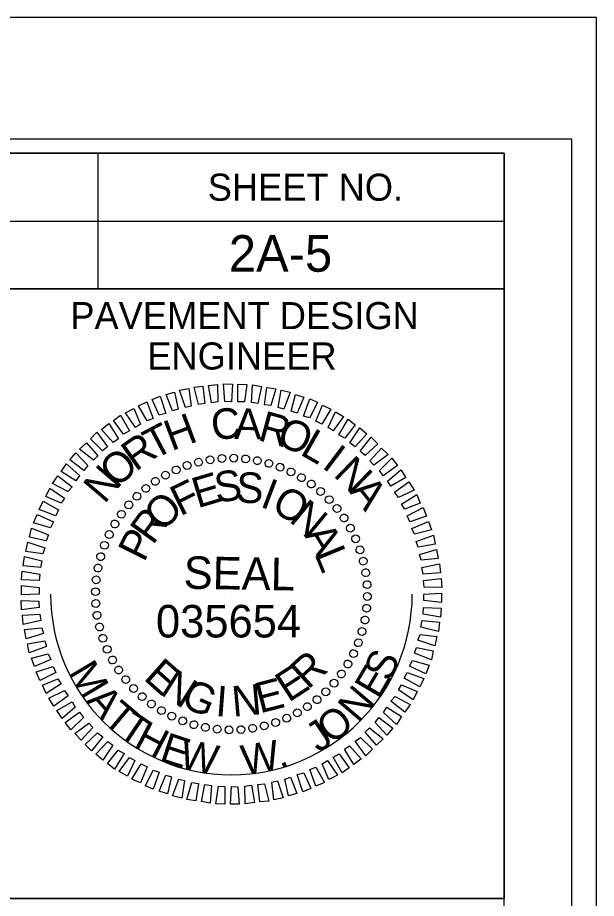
# Model space of a CAD drawing. Extents: x 957297 to 961629, y 830661 to 840840.
# Drawn here: x 960288 to 960394.8, y 835525.5 to 835688 of the extents above; entities that cross this region are included whole.
import ezdxf

# ---------------------------------------------------------------- set-up
doc = ezdxf.new("R2010")
doc.units = 0
for name, color, linetype in [('Scratch_Level_0', 7, 'Continuous'), ('Sheet Data Field CELL', 7, 'Continuous'), ('Sheet Plot Border Inside CELL', 7, 'Continuous'), ('Sheet Plot Border Outside CELL', 7, 'Continuous'), ('Sheet Professional Seal CELL', 7, 'Continuous'), ('Sheet Profile Grid Minor CELL', 7, 'Continuous'), ('Sheet Sticker Exception Certification CELL', 7, 'Continuous'), ('Sheet Typical CELL', 7, 'Continuous')]:
    doc.layers.add(name, color=color, linetype=linetype)

msp = doc.modelspace()

# ---------------------------------------------------------------- linework, layer by layer
at = {"layer": 'Scratch_Level_0'}
msp.add_arc((960327.47, 835581.64), 33.36, 180, 360, dxfattribs=at)
at = {"layer": 'Sheet Plot Border Inside CELL'}
msp.add_lwpolyline([(960390.3, 835665.58), (958723.8, 835665.58), (958723.8, 834610.48), (960390.3, 834610.48)], close=True, dxfattribs=at)
at = {"layer": 'Sheet Plot Border Outside CELL'}
msp.add_lwpolyline([(960394.8, 835688.03), (958710.8, 835688.03), (958710.8, 834588.03), (960394.8, 834588.03)], close=True, dxfattribs=at)
at = {"layer": 'Sheet Professional Seal CELL'}
for p, q in [((960321.37, 835605.99), (960321.37, 835605.99)), ((960323.57, 835606.39), (960323.57, 835606.39)), ((960325.72, 835606.69), (960325.72, 835606.69)), ((960327.92, 835606.74), (960327.92, 835606.74)), ((960330.12, 835606.59), (960330.12, 835606.59)), ((960332.27, 835606.24), (960332.27, 835606.24)), ((960334.37, 835605.79), (960334.37, 835605.79)), ((960317.27, 835604.59), (960317.27, 835604.59)), ((960319.27, 835605.39), (960319.27, 835605.39)), ((960336.47, 835605.09), (960336.47, 835605.09)), ((960338.47, 835604.19), (960338.47, 835604.19)), ((960315.32, 835603.59), (960315.32, 835603.59)), ((960340.42, 835603.19), (960340.42, 835603.19)), ((960311.67, 835601.19), (960311.67, 835601.19)), ((960313.42, 835602.44), (960313.42, 835602.44)), ((960342.22, 835601.94), (960342.22, 835601.94)), ((960310.02, 835599.69), (960310.02, 835599.69)), ((960343.97, 835600.59), (960343.97, 835600.59)), ((960308.52, 835598.14), (960308.52, 835598.14)), ((960345.52, 835599.09), (960345.52, 835599.09)), ((960307.17, 835596.39), (960307.17, 835596.39)), ((960347.02, 835597.44), (960347.02, 835597.44)), ((960305.92, 835594.59), (960305.92, 835594.59)), ((960348.27, 835595.69), (960348.27, 835595.69)), ((960349.42, 835593.79), (960349.42, 835593.79)), ((960304.92, 835592.64), (960304.92, 835592.64)), ((960350.42, 835591.84), (960350.42, 835591.84)), ((960304.02, 835590.64), (960304.02, 835590.64)), ((960351.22, 835589.84), (960351.22, 835589.84)), ((960303.32, 835588.54), (960303.32, 835588.54)), ((960302.87, 835586.44), (960302.87, 835586.44)), ((960351.82, 835587.74), (960351.82, 835587.74)), ((960352.22, 835585.54), (960352.22, 835585.54)), ((960302.52, 835584.29), (960302.52, 835584.29)), ((960352.52, 835583.39), (960352.52, 835583.39)), ((960302.37, 835582.09), (960302.37, 835582.09)), ((960327.47, 835581.64), (960327.47, 835581.64)), ((960302.42, 835579.89), (960302.42, 835579.89)), ((960352.57, 835581.19), (960352.57, 835581.19)), ((960352.42, 835578.99), (960352.42, 835578.99)), ((960302.72, 835577.74), (960302.72, 835577.74)), ((960352.07, 835576.84), (960352.07, 835576.84)), ((960303.12, 835575.54), (960303.12, 835575.54)), ((960303.72, 835573.44), (960303.72, 835573.44)), ((960351.62, 835574.74), (960351.62, 835574.74)), ((960350.92, 835572.64), (960350.92, 835572.64)), ((960304.52, 835571.44), (960304.52, 835571.44)), ((960350.02, 835570.64), (960350.02, 835570.64)), ((960305.52, 835569.49), (960305.52, 835569.49)), ((960349.02, 835568.69), (960349.02, 835568.69)), ((960306.67, 835567.59), (960306.67, 835567.59)), ((960347.77, 835566.89), (960347.77, 835566.89)), ((960307.92, 835565.84), (960307.92, 835565.84)), ((960346.42, 835565.14), (960346.42, 835565.14)), ((960309.42, 835564.19), (960309.42, 835564.19)), ((960344.92, 835563.59), (960344.92, 835563.59)), ((960310.97, 835562.69), (960310.97, 835562.69)), ((960343.27, 835562.09), (960343.27, 835562.09)), ((960312.72, 835561.34), (960312.72, 835561.34)), ((960341.52, 835560.84), (960341.52, 835560.84)), ((960314.52, 835560.09), (960314.52, 835560.09)), ((960316.47, 835559.09), (960316.47, 835559.09)), ((960337.67, 835558.69), (960337.67, 835558.69)), ((960339.62, 835559.69), (960339.62, 835559.69)), ((960318.47, 835558.19), (960318.47, 835558.19)), ((960320.57, 835557.49), (960320.57, 835557.49)), ((960322.67, 835557.04), (960322.67, 835557.04)), ((960333.57, 835557.29), (960333.57, 835557.29)), ((960335.67, 835557.89), (960335.67, 835557.89)), ((960324.82, 835556.69), (960324.82, 835556.69)), ((960327.02, 835556.54), (960327.02, 835556.54)), ((960329.22, 835556.59), (960329.22, 835556.59)), ((960331.37, 835556.89), (960331.37, 835556.89))]:
    msp.add_line(p, q, dxfattribs=at)
for points in [[(960326.27, 835617.19), (960326.02, 835620.44), (960327.67, 835620.39), (960327.47, 835617.14)], [(960316.57, 835615.44), (960315.42, 835618.44), (960316.97, 835618.89), (960317.62, 835615.79)], [(960318.97, 835616.09), (960317.92, 835619.24), (960319.62, 835619.59), (960320.02, 835616.34)], [(960321.37, 835616.64), (960320.57, 835619.84), (960322.22, 835619.99), (960322.57, 835616.79)], [(960323.77, 835616.94), (960323.22, 835620.14), (960324.92, 835620.34), (960324.97, 835617.09)], [(960328.67, 835617.14), (960328.67, 835620.39), (960330.32, 835620.34), (960329.87, 835617.09)], [(960331.17, 835616.99), (960331.37, 835620.24), (960333.02, 835619.94), (960332.37, 835616.79)], [(960333.57, 835616.59), (960334.02, 835619.79), (960335.67, 835619.54), (960334.77, 835616.44)], [(960336.12, 835616.04), (960336.62, 835619.29), (960338.32, 835618.89), (960337.17, 835615.79)], [(960314.12, 835614.64), (960312.82, 835617.54), (960314.32, 835618.14), (960315.37, 835614.94)], [(960338.52, 835615.39), (960339.27, 835618.49), (960340.82, 835617.99), (960339.57, 835615.04)], [(960340.77, 835614.49), (960341.92, 835617.64), (960343.32, 835617.04), (960341.92, 835614.14)], [(960309.77, 835612.39), (960307.92, 835615.09), (960309.47, 835615.89), (960310.72, 835612.99)], [(960311.92, 835613.59), (960310.32, 835616.39), (960311.87, 835617.09), (960313.02, 835614.04)], [(960343.02, 835613.54), (960344.27, 835616.49), (960345.82, 835615.79), (960344.12, 835612.99)], [(960307.57, 835611.14), (960305.72, 835613.69), (960307.02, 835614.64), (960308.67, 835611.74)], [(960345.32, 835612.39), (960346.67, 835615.24), (960348.17, 835614.39), (960346.27, 835611.79)], [(960347.27, 835611.04), (960349.02, 835613.94), (960350.32, 835612.89), (960348.37, 835610.44)], [(960305.67, 835609.64), (960303.52, 835612.04), (960304.87, 835613.09), (960306.62, 835610.29)], [(960349.32, 835609.54), (960351.17, 835612.29), (960352.47, 835611.19), (960350.27, 835608.84)], [(960303.67, 835608.09), (960301.47, 835610.29), (960302.67, 835611.49), (960304.62, 835608.79)], [(960302.02, 835606.34), (960299.47, 835608.39), (960300.72, 835609.54), (960302.82, 835607.14)], [(960351.22, 835607.99), (960353.27, 835610.59), (960354.47, 835609.39), (960352.17, 835607.24)], [(960300.27, 835604.44), (960297.67, 835606.39), (960298.77, 835607.69), (960300.97, 835605.34)], [(960353.02, 835606.24), (960355.17, 835608.59), (960356.37, 835607.39), (960353.77, 835605.44)], [(960354.77, 835604.44), (960357.07, 835606.69), (960358.12, 835605.34), (960355.47, 835603.44)], [(960298.77, 835602.54), (960296.07, 835604.24), (960297.02, 835605.69), (960299.42, 835603.49)], [(960356.27, 835602.49), (960358.72, 835604.59), (960359.67, 835603.14), (960356.87, 835601.54)], [(960297.27, 835600.54), (960294.47, 835602.04), (960295.47, 835603.44), (960298.07, 835601.44)], [(960296.07, 835598.39), (960293.22, 835599.64), (960293.97, 835601.19), (960296.67, 835599.34)], [(960357.57, 835600.44), (960360.22, 835602.34), (960361.17, 835600.84), (960358.27, 835599.44)], [(960358.87, 835598.24), (960361.67, 835599.99), (960362.32, 835598.44), (960359.47, 835597.29)], [(960295.07, 835596.09), (960291.97, 835597.24), (960292.72, 835598.79), (960295.57, 835597.19)], [(960294.07, 835593.89), (960290.97, 835594.79), (960291.62, 835596.34), (960294.62, 835594.94)], [(960359.87, 835596.09), (960362.82, 835597.59), (960363.47, 835595.99), (960360.37, 835594.99)], [(960360.77, 835593.74), (960363.82, 835595.04), (960364.37, 835593.49), (960361.27, 835592.69)], [(960293.32, 835591.49), (960290.22, 835592.14), (960290.57, 835593.79), (960293.72, 835592.54)], [(960292.67, 835589.09), (960289.57, 835589.49), (960289.92, 835591.19), (960293.07, 835590.14)], [(960361.57, 835591.34), (960364.77, 835592.49), (960365.07, 835590.84), (960361.92, 835590.29)], [(960362.17, 835588.94), (960365.32, 835589.89), (960365.62, 835588.19), (960362.47, 835587.89)], [(960292.27, 835586.54), (960289.07, 835586.84), (960289.27, 835588.54), (960292.52, 835587.74)], [(960362.62, 835586.54), (960365.87, 835587.24), (960366.02, 835585.54), (960362.82, 835585.34)], [(960292.02, 835584.14), (960288.77, 835584.24), (960288.87, 835585.89), (960292.12, 835585.34)], [(960291.97, 835581.64), (960288.72, 835581.49), (960288.72, 835583.19), (960291.97, 835582.84)], [(960362.92, 835584.14), (960366.17, 835584.54), (960366.27, 835582.84), (960363.02, 835582.94)], [(960362.97, 835581.64), (960366.22, 835581.79), (960366.22, 835580.09), (960362.97, 835580.44)], [(960292.02, 835579.14), (960288.77, 835578.74), (960288.67, 835580.44), (960291.92, 835580.34)], [(960362.92, 835579.14), (960366.17, 835579.04), (960366.07, 835577.39), (960362.82, 835577.94)], [(960292.32, 835576.74), (960289.07, 835576.04), (960288.92, 835577.74), (960292.12, 835577.94)], [(960362.67, 835576.74), (960365.87, 835576.44), (960365.67, 835574.74), (960362.42, 835575.54)], [(960292.77, 835574.34), (960289.62, 835573.39), (960289.32, 835575.09), (960292.47, 835575.39)], [(960362.27, 835574.19), (960365.37, 835573.79), (960365.02, 835572.09), (960361.87, 835573.14)], [(960293.37, 835571.94), (960290.17, 835570.79), (960289.87, 835572.44), (960293.02, 835572.99)], [(960361.62, 835571.79), (960364.72, 835571.14), (960364.37, 835569.49), (960361.22, 835570.74)], [(960294.17, 835569.54), (960291.12, 835568.24), (960290.57, 835569.79), (960293.67, 835570.59)], [(960360.87, 835569.39), (960363.97, 835568.49), (960363.32, 835566.94), (960360.32, 835568.34)], [(960295.07, 835567.19), (960292.12, 835565.69), (960291.47, 835567.29), (960294.57, 835568.29)], [(960359.87, 835567.19), (960362.97, 835566.04), (960362.22, 835564.49), (960359.37, 835566.09)], [(960296.07, 835565.04), (960293.27, 835563.29), (960292.62, 835564.84), (960295.47, 835565.99)], [(960297.37, 835562.84), (960294.72, 835560.94), (960293.77, 835562.44), (960296.67, 835563.84)], [(960358.87, 835564.89), (960361.72, 835563.64), (960360.97, 835562.09), (960358.27, 835563.94)], [(960357.67, 835562.74), (960360.47, 835561.24), (960359.47, 835559.84), (960356.87, 835561.84)], [(960298.67, 835560.79), (960296.22, 835558.69), (960295.27, 835560.14), (960298.07, 835561.74)], [(960356.17, 835560.74), (960358.87, 835559.04), (960357.92, 835557.59), (960355.52, 835559.79)], [(960300.17, 835558.84), (960297.87, 835556.59), (960296.82, 835557.94), (960299.47, 835559.84)], [(960354.67, 835558.84), (960357.27, 835556.89), (960356.17, 835555.59), (960353.97, 835557.94)], [(960301.92, 835557.04), (960299.77, 835554.69), (960298.57, 835555.89), (960301.17, 835557.84)], [(960303.72, 835555.29), (960301.67, 835552.69), (960300.47, 835553.89), (960302.77, 835556.04)], [(960352.92, 835556.94), (960355.47, 835554.89), (960354.22, 835553.74), (960352.12, 835556.14)], [(960305.62, 835553.74), (960303.77, 835550.99), (960302.47, 835552.09), (960304.67, 835554.44)], [(960351.27, 835555.19), (960353.47, 835552.99), (960352.27, 835551.79), (960350.32, 835554.49)], [(960307.67, 835552.24), (960305.92, 835549.34), (960304.62, 835550.39), (960306.57, 835552.84)], [(960347.37, 835552.14), (960349.22, 835549.59), (960347.92, 835548.64), (960346.27, 835551.54)], [(960349.27, 835553.64), (960351.42, 835551.24), (960350.07, 835550.19), (960348.32, 835552.99)], [(960309.62, 835550.89), (960308.27, 835548.04), (960306.77, 835548.89), (960308.67, 835551.49)], [(960345.17, 835550.89), (960347.02, 835548.19), (960345.47, 835547.39), (960344.22, 835550.29)], [(960311.92, 835549.74), (960310.67, 835546.79), (960309.12, 835547.49), (960310.82, 835550.29)], [(960314.17, 835548.79), (960313.02, 835545.64), (960311.62, 835546.24), (960313.02, 835549.14)], [(960343.02, 835549.69), (960344.62, 835546.89), (960343.07, 835546.19), (960341.92, 835549.24)], [(960316.42, 835547.89), (960315.67, 835544.79), (960314.12, 835545.29), (960315.37, 835548.24)], [(960318.82, 835547.24), (960318.32, 835543.99), (960316.62, 835544.39), (960317.77, 835547.49)], [(960338.37, 835547.84), (960339.52, 835544.84), (960337.97, 835544.39), (960337.32, 835547.49)], [(960340.82, 835548.64), (960342.12, 835545.74), (960340.62, 835545.14), (960339.57, 835548.34)], [(960321.37, 835546.69), (960320.92, 835543.49), (960319.27, 835543.74), (960320.17, 835546.84)], [(960323.77, 835546.29), (960323.57, 835543.04), (960321.92, 835543.34), (960322.57, 835546.49)], [(960326.27, 835546.14), (960326.27, 835542.89), (960324.62, 835542.94), (960325.07, 835546.19)], [(960328.67, 835546.09), (960328.92, 835542.84), (960327.27, 835542.89), (960327.47, 835546.14)], [(960331.17, 835546.34), (960331.72, 835543.14), (960330.02, 835542.94), (960329.97, 835546.19)], [(960333.57, 835546.64), (960334.37, 835543.44), (960332.72, 835543.29), (960332.37, 835546.49)], [(960335.97, 835547.19), (960337.02, 835544.04), (960335.32, 835543.69), (960334.92, 835546.94)]]:
    msp.add_lwpolyline(points, close=True, dxfattribs=at)
for centre, major_axis in [((960325.72, 835606.66), (-0.05, 0.718)), ((960327.9, 835606.72), (0.013, 0.72)), ((960319.3, 835605.36), (-0.234, 0.681)), ((960321.4, 835605.98), (-0.174, 0.699)), ((960323.54, 835606.41), (-0.113, 0.711)), ((960330.09, 835606.58), (0.075, 0.716)), ((960332.25, 835606.26), (0.137, 0.707)), ((960334.38, 835605.75), (0.198, 0.692)), ((960336.45, 835605.06), (0.258, 0.672)), ((960315.31, 835603.58), (-0.349, 0.63)), ((960317.27, 835604.55), (-0.293, 0.658)), ((960338.46, 835604.18), (0.316, 0.647)), ((960313.44, 835602.43), (-0.403, 0.597)), ((960340.38, 835603.14), (0.371, 0.617)), ((960342.21, 835601.93), (0.423, 0.582)), ((960311.68, 835601.13), (-0.453, 0.56)), ((960343.92, 835600.57), (0.472, 0.543)), ((960310.04, 835599.68), (-0.5, 0.518)), ((960345.51, 835599.06), (0.518, 0.5)), ((960308.54, 835598.1), (-0.543, 0.472)), ((960346.96, 835597.43), (0.56, 0.453)), ((960307.18, 835596.38), (-0.582, 0.423)), ((960348.26, 835595.67), (0.597, 0.403)), ((960305.97, 835594.56), (-0.617, 0.371)), ((960349.4, 835593.8), (0.63, 0.349)), ((960304.92, 835592.64), (-0.647, 0.316)), ((960304.05, 835590.63), (-0.672, 0.258)), ((960350.38, 835591.84), (0.658, 0.293)), ((960351.18, 835589.81), (0.681, 0.234)), ((960303.36, 835588.55), (-0.692, 0.198)), ((960351.8, 835587.71), (0.699, 0.174)), ((960302.85, 835586.43), (-0.707, 0.137)), ((960352.24, 835585.57), (0.711, 0.113)), ((960302.52, 835584.26), (-0.716, 0.075)), ((960352.49, 835583.39), (0.718, 0.05)), ((960302.39, 835582.08), (-0.72, 0.013)), ((960352.54, 835581.2), (0.72, -0.013)), ((960302.45, 835579.89), (-0.718, -0.05)), ((960352.41, 835579.02), (0.716, -0.075)), ((960302.69, 835577.72), (-0.711, -0.113)), ((960352.09, 835576.86), (0.707, -0.137)), ((960303.13, 835575.57), (-0.699, -0.174)), ((960351.57, 835574.73), (0.692, -0.198)), ((960303.75, 835573.48), (-0.681, -0.234)), ((960350.88, 835572.65), (0.672, -0.258)), ((960304.55, 835571.44), (-0.658, -0.293)), ((960305.53, 835569.48), (-0.63, -0.349)), ((960350.01, 835570.65), (0.647, -0.316)), ((960306.67, 835567.62), (-0.597, -0.403)), ((960348.96, 835568.72), (0.617, -0.371)), ((960347.76, 835566.9), (0.582, -0.423)), ((960307.98, 835565.86), (-0.56, -0.453)), ((960346.39, 835565.19), (0.543, -0.472)), ((960309.43, 835564.22), (-0.518, -0.5)), ((960311.01, 835562.71), (-0.472, -0.543)), ((960344.89, 835563.6), (0.5, -0.518)), ((960312.72, 835561.35), (-0.423, -0.582)), ((960343.25, 835562.15), (0.453, -0.56)), ((960314.55, 835560.14), (-0.371, -0.617)), ((960339.63, 835559.71), (0.349, -0.63)), ((960341.49, 835560.85), (0.403, -0.597)), ((960316.47, 835559.1), (-0.316, -0.647)), ((960318.48, 835558.23), (-0.258, -0.672)), ((960335.63, 835557.93), (0.234, -0.681)), ((960337.67, 835558.73), (0.293, -0.658)), ((960320.55, 835557.53), (-0.198, -0.692)), ((960322.68, 835557.02), (-0.137, -0.707)), ((960324.84, 835556.7), (-0.075, -0.716)), ((960327.03, 835556.57), (-0.013, -0.72)), ((960329.22, 835556.62), (0.05, -0.718)), ((960331.39, 835556.87), (0.113, -0.711)), ((960333.53, 835557.31), (0.174, -0.699))]:
    msp.add_ellipse(centre, major_axis=major_axis, ratio=0.999708, dxfattribs=at)
at = {"layer": 'Sheet Sticker Exception Certification CELL'}
msp.add_line((960177.75, 835525.48), (960377.79, 835525.48), dxfattribs=at)
at = {"layer": 'Sheet Typical CELL'}
for p, q in [((960302.8, 835662.98), (960302.8, 835637.98)), ((960177.75, 835650.48), (960377.8, 835650.48))]:
    msp.add_line(p, q, dxfattribs=at)
for points in [[(960377.8, 835663.03), (958877.8, 835663.03), (958877.8, 834613.03), (960377.8, 834613.03)], [(960177.75, 835663.03), (960377.8, 835663.03), (960377.8, 835637.98), (960177.75, 835637.98)], [(960277.8, 835637.98), (960377.8, 835637.98), (960377.8, 835525.48), (960277.8, 835525.48)]]:
    msp.add_lwpolyline(points, close=True, dxfattribs=at)

# ---------------------------------------------------------------- texts
at = {"layer": 'Sheet Data Field CELL'}
msp.add_text('2A-5', height=6.75, dxfattribs=at).set_placement((960326.99, 835641.13))
at = {"layer": 'Sheet Professional Seal CELL'}
for s, height, rotation, p in [('C', 5.64, 6.2199, (960324.02, 835609.99)), ('A', 5.64, 359.0203, (960327.97, 835610.29)), ('H', 5.64, 20.6195, (960316.42, 835607.99)), ('R', 5.64, 344.6211, (960332.17, 835610.09)), ('O', 5.64, 337.4212, (960335.52, 835609.34)), ('T', 5.64, 27.8198, (960313.17, 835606.34)), ('R', 5.64, 35.0205, (960309.77, 835604.14)), ('L', 5.64, 330.2209, (960339.92, 835607.49)), ('I', 5.64, 323.0201, (960343.97, 835605.09)), ('O', 5.64, 42.2217, (960306.32, 835601.04)), ('N', 5.64, 315.8189, (960346.12, 835603.54)), ('N', 5.64, 49.4235, (960304.02, 835598.14)), ('S', 5.64, 7.2556, (960324.67, 835598.49)), ('S', 5.64, 357.9004, (960328.27, 835598.54)), ('F', 5.64, 25.967, (960318.02, 835595.94)), ('E', 5.64, 16.6111, (960321.22, 835597.44)), ('I', 5.64, 339.1896, (960332.57, 835597.84)), ('O', 5.64, 329.8335, (960334.57, 835597.14)), ('A', 5.64, 308.6172, (960349.07, 835600.59)), ('O', 5.64, 44.6812, (960314.72, 835592.99)), ('N', 5.64, 320.4766, (960337.92, 835595.14)), ('R', 5.64, 54.0397, (960312.97, 835590.54)), ('P', 5.64, 63.3989, (960311.37, 835587.34)), ('A', 5.64, 301.7603, (960340.77, 835592.54)), ('L', 5.64, 292.4008, (960342.72, 835589.09)), ('SEAL', 5.998, 359, (960318.62, 835582.64)), ('R', 5.64, 42.4814, (960341.57, 835563.89)), ('E', 5.64, 318.2769, (960311.07, 835565.99)), ('E', 5.64, 33.1241, (960338.02, 835561.54)), ('N', 5.64, 327.634, (960314.07, 835563.29)), ('G', 5.64, 336.9902, (960317.87, 835561.04)), ('E', 5.64, 14.4118, (960332.72, 835559.59)), ('I', 5.64, 355.7012, (960324.42, 835559.14)), ('N', 5.64, 5.0564, (960327.77, 835558.99))]:
    msp.add_text(s, height=height, rotation=rotation, dxfattribs=at).set_placement(p)
at = {"layer": 'Sheet Profile Grid Minor CELL'}
msp.add_text('035654', height=5.998, dxfattribs=at).set_placement((960313.55, 835573.63))
for s, rotation, p in [('S', 66.1201, (960356.72, 835565.29)), ('M', 300.9117, (960297.24, 835567.17)), ('E', 59.5371, (960354.65, 835562.05)), ('A', 311.5876, (960300.45, 835561.82)), ('N', 49.6054, (960350.86, 835557.65)), ('T', 319.7734, (960303.55, 835558.18)), ('O', 38.9008, (960346, 835553.73)), ('T', 326.0702, (960306.26, 835555.69)), ('H', 332.3669, (960309.24, 835553.53)), ('J', 34.0323, (960343.56, 835552.25)), ('E', 341.6117, (960313.99, 835550.96)), ('W', 348.1947, (960317.6, 835549.62)), ('W', 9.2459, (960329.76, 835548.21)), ('.', 20.852, (960336.44, 835549.36))]:
    msp.add_text(s, height=5.5, rotation=rotation, dxfattribs=at).set_placement(p)
at = {"layer": 'Sheet Typical CELL'}
for s, height, p in [('SHEET NO.', 5, (960323.1, 835654.23)), ('PAVEMENT DESIGN', 5.0001, (960297.75, 835630.53)), ('ENGINEER', 5, (960311.95, 835623.08))]:
    msp.add_text(s, height=height, dxfattribs=at).set_placement(p)

doc.saveas('drawing.dxf')
